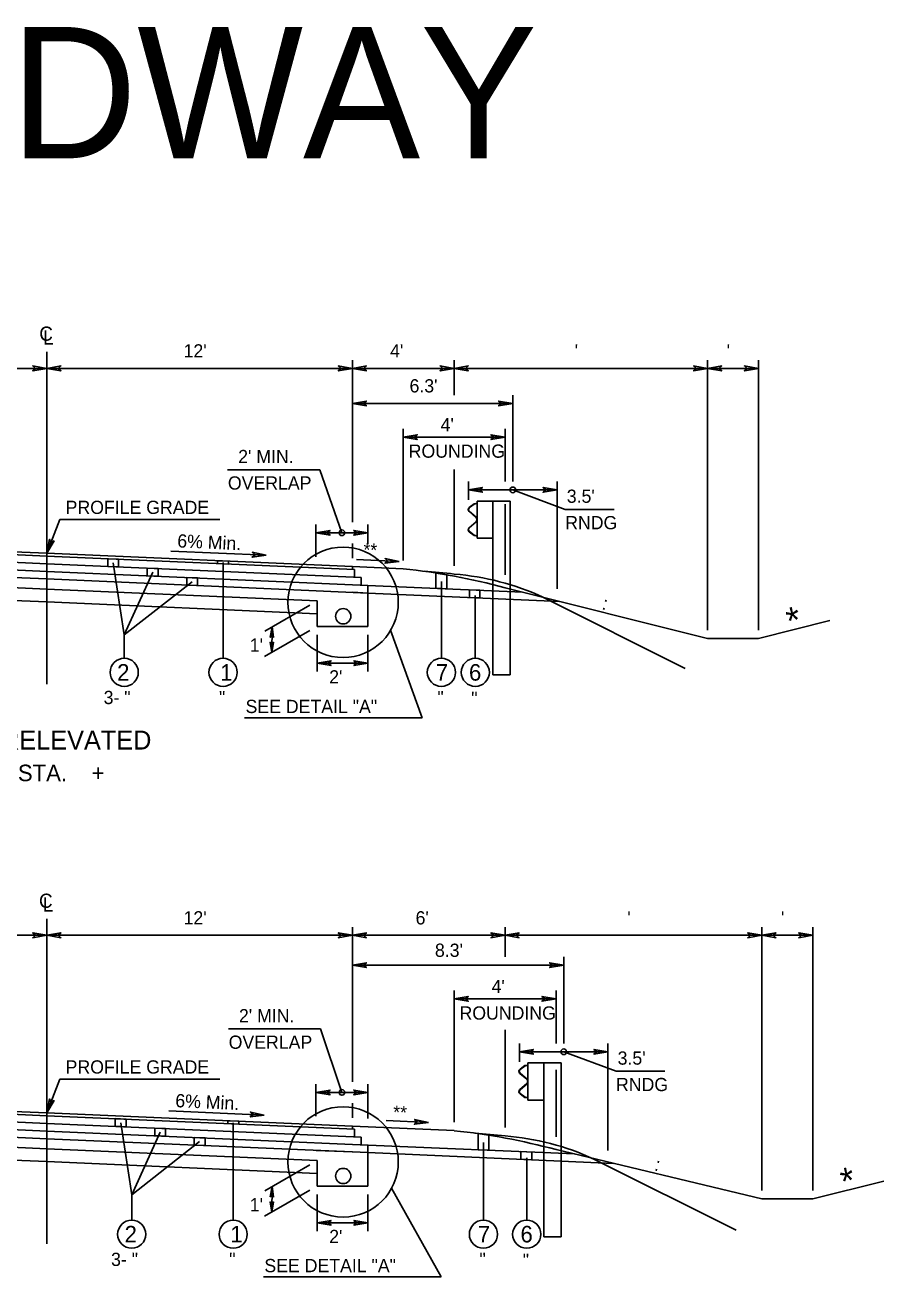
# Model space of a CAD drawing. Extents: x -540 to 1231, y -564 to 421.
# Drawn here: x 1120.2 to 1211.1, y 191.2 to 323.7 of the extents above; entities that cross this region are included whole.
import ezdxf

# ---------------------------------------------------------------- set-up
doc = ezdxf.new("R2010")
doc.units = 0
doc.layers.add('1', color=7, linetype='Continuous')
doc.layers.add('Des_ Drain_ Ftrs', color=7, linetype='Continuous')

msp = doc.modelspace()

# ---------------------------------------------------------------- linework, layer by layer
at = {"layer": '1'}
for p, q in [((1122.51, 253.91), (1122.51, 289.09)), ((1154.84, 271.06), (1154.84, 288.21)), ((1165.61, 284.5), (1165.61, 288.21)), ((1192.43, 259.63), (1192.43, 288.21)), ((1197.82, 259.63), (1197.82, 288.21)), ((1122.51, 287.33), (1090.18, 287.33)), ((1122.51, 287.33), (1154.84, 287.33)), ((1154.84, 287.33), (1165.61, 287.33)), ((1165.61, 287.33), (1192.43, 287.33)), ((1192.43, 287.33), (1197.82, 287.33)), ((1154.84, 283.62), (1171.81, 283.62)), ((1171.81, 275.35), (1171.81, 284.5)), ((1160.23, 267), (1160.23, 280.93)), ((1171, 275.35), (1171, 280.93)), ((1160.23, 280.05), (1171, 280.05)), ((1141.63, 276.6), (1151.4, 276.6)), ((1153.74, 269.93), (1151.4, 276.6)), ((1165.61, 266.44), (1165.61, 276.64)), ((1167.12, 273.4), (1167.12, 275.35)), ((1167.12, 274.47), (1176.51, 274.47)), ((1171.81, 274.47), (1177.37, 272.4)), ((1176.51, 263.99), (1176.51, 275.35)), ((1167.72, 273), (1167.2, 272.61)), ((1167.73, 272.97), (1167.22, 272.59)), ((1168.03, 273.06), (1167.72, 273)), ((1168.03, 273.03), (1167.73, 272.97)), ((1168.03, 273.28), (1168.03, 269.35)), ((1168.03, 273.28), (1169.72, 273.28)), ((1169.72, 273.28), (1169.72, 254.89)), ((1171.54, 273.28), (1169.72, 273.28)), ((1171, 265.47), (1171, 272.97)), ((1171.54, 273.28), (1171.54, 254.89)), ((1167.19, 272.18), (1167.92, 271.54)), ((1167.21, 272.2), (1167.94, 271.57)), ((1177.37, 272.4), (1182.53, 272.4)), ((1122.51, 267.76), (1123.88, 271.34)), ((1140.8, 271.34), (1123.88, 271.34)), ((1150.99, 267.4), (1150.99, 270.81)), ((1156.48, 268.73), (1156.48, 270.81)), ((1167.92, 271.09), (1167.19, 270.46)), ((1167.94, 271.07), (1167.21, 270.44)), ((1168, 271.36), (1168, 271.28)), ((1168.03, 271.36), (1168.03, 271.28)), ((1122.51, 267.76), (1090.17, 269.18)), ((1150.99, 269.93), (1156.48, 269.93)), ((1167.2, 270.03), (1167.72, 269.64)), ((1167.22, 270.05), (1167.73, 269.66)), ((1167.72, 269.64), (1168.03, 269.58)), ((1167.73, 269.66), (1168.03, 269.61)), ((1168.03, 269.35), (1169.72, 269.35)), ((1122.51, 266.65), (1088.91, 268.12)), ((1122.51, 267.46), (1089.83, 268.89)), ((1154.84, 266.35), (1122.51, 267.76)), ((1135.62, 267.99), (1145.73, 267.55)), ((1154.84, 267.23), (1154.84, 268.8)), ((1122.51, 265.84), (1087.99, 267.35)), ((1122.51, 265.04), (1088, 266.54)), ((1155.08, 266.04), (1122.51, 267.46)), ((1155.78, 265.2), (1122.51, 266.65)), ((1129.53, 266.75), (1130.7, 259.13)), ((1141.16, 266.79), (1141.16, 256.64)), ((1160.23, 266.12), (1154.84, 266.35)), ((1154.84, 266.35), (1154.84, 266.05)), ((1159.78, 266.89), (1155.29, 267.09)), ((1122.51, 263.96), (1093.38, 265.23)), ((1156.48, 264.36), (1122.51, 265.84)), ((1151, 263.79), (1122.51, 265.04)), ((1133.71, 265.77), (1130.7, 259.13)), ((1155.08, 266.04), (1155.08, 265.23)), ((1155.78, 265.2), (1155.78, 264.39)), ((1167.12, 265.34), (1167.12, 265.34)), ((1122.51, 262.61), (1093.38, 263.88)), ((1151.1, 262.71), (1122.51, 263.96)), ((1137.88, 264.75), (1130.7, 259.13)), ((1156.48, 263.55), (1151, 263.79)), ((1156.48, 264.36), (1156.48, 263.55)), ((1172.83, 263.65), (1156.48, 264.36)), ((1164.26, 264.76), (1164.26, 256.64)), ((1171, 264.11), (1192.43, 258.75)), ((1151.1, 261.36), (1122.51, 262.61)), ((1151.1, 260.01), (1151.1, 262.71)), ((1151.1, 262.71), (1151.1, 262.71)), ((1156.5, 263.55), (1154.84, 263.63)), ((1156.48, 260.01), (1156.48, 263.55)), ((1176.75, 262.67), (1156.48, 263.55)), ((1167.85, 263.28), (1167.85, 256.64)), ((1175.01, 263.11), (1190.06, 255.58)), ((1150.33, 262.27), (1145.58, 259.52)), ((1146.34, 259.96), (1146.32, 257.26)), ((1151.1, 260.01), (1156.48, 260.01)), ((1205.35, 260.63), (1197.82, 258.75)), ((1130.7, 259.13), (1130.7, 256.64)), ((1150.33, 259.57), (1145.56, 256.82)), ((1151.1, 259.13), (1151.1, 255.25)), ((1156.48, 259.13), (1156.48, 255.25)), ((1158.89, 259.62), (1162.22, 250.35)), ((1192.43, 258.75), (1197.82, 258.75)), ((1151.1, 256.13), (1156.48, 256.13)), ((1171.54, 254.89), (1169.72, 254.89)), ((1143.44, 250.35), (1162.22, 250.35)), ((1122.51, 194.69), (1122.51, 229.09)), ((1154.84, 211.83), (1154.84, 228.21)), ((1171, 225.05), (1171, 228.21)), ((1198.17, 200.31), (1198.17, 228.21)), ((1203.56, 200.31), (1203.56, 228.21)), ((1122.51, 227.33), (1090.18, 227.33)), ((1122.51, 227.33), (1154.84, 227.33)), ((1154.84, 227.33), (1171, 227.33)), ((1171, 227.33), (1198.17, 227.33)), ((1198.17, 227.33), (1203.56, 227.33)), ((1154.84, 224.17), (1177.2, 224.17)), ((1177.2, 215.89), (1177.2, 225.05)), ((1165.61, 207.54), (1165.61, 221.48)), ((1176.39, 215.89), (1176.39, 221.48)), ((1165.61, 220.6), (1176.39, 220.6)), ((1141.72, 217.42), (1151.48, 217.42)), ((1153.74, 210.71), (1151.48, 217.42)), ((1171, 206.98), (1171, 217.33)), ((1172.51, 213.94), (1172.51, 215.89)), ((1172.51, 215.01), (1181.89, 215.01)), ((1177.2, 215.01), (1182.75, 212.94)), ((1181.89, 204.55), (1181.89, 215.89)), ((1173.1, 213.55), (1172.59, 213.16)), ((1173.12, 213.52), (1172.6, 213.13)), ((1173.42, 213.6), (1173.1, 213.55)), ((1173.42, 213.57), (1173.12, 213.52)), ((1173.42, 213.83), (1173.42, 209.9)), ((1173.42, 213.83), (1175.1, 213.83)), ((1175.1, 213.83), (1175.1, 195.43)), ((1176.93, 213.83), (1175.1, 213.83)), ((1176.93, 213.83), (1176.93, 195.43)), ((1122.51, 208.54), (1123.88, 212.12)), ((1140.8, 212.12), (1123.88, 212.12)), ((1172.57, 212.72), (1173.3, 212.09)), ((1172.59, 212.75), (1173.32, 212.11)), ((1176.39, 206.02), (1176.39, 213.09)), ((1182.75, 212.94), (1187.91, 212.94)), ((1150.99, 208.18), (1150.99, 211.59)), ((1150.99, 210.71), (1156.48, 210.71)), ((1156.48, 207.94), (1156.48, 211.59)), ((1173.3, 211.64), (1172.57, 211)), ((1173.32, 211.62), (1172.59, 210.98)), ((1173.39, 211.9), (1173.39, 211.83)), ((1173.42, 211.9), (1173.42, 211.83)), ((1122.51, 208.24), (1089.83, 209.67)), ((1122.51, 208.54), (1090.17, 209.95)), ((1154.84, 208.01), (1154.84, 209.58)), ((1172.59, 210.57), (1173.1, 210.18)), ((1172.6, 210.59), (1173.12, 210.21)), ((1173.1, 210.18), (1173.42, 210.13)), ((1173.12, 210.21), (1173.42, 210.16)), ((1173.42, 209.9), (1175.1, 209.9)), ((1122.51, 206.62), (1087.99, 208.13)), ((1122.51, 207.43), (1088.91, 208.9)), ((1154.84, 207.13), (1122.51, 208.54)), ((1155.08, 206.82), (1122.51, 208.24)), ((1135.41, 208.75), (1145.52, 208.31)), ((1122.51, 205.81), (1087.99, 207.32)), ((1155.78, 205.98), (1122.51, 207.43)), ((1130.33, 207.49), (1131.49, 199.87)), ((1142.23, 207.5), (1142.23, 197.19)), ((1165.61, 206.66), (1154.84, 207.13)), ((1154.84, 207.13), (1154.84, 206.83)), ((1155.08, 206.82), (1155.08, 206.01)), ((1162.9, 207.52), (1158.41, 207.72)), ((1122.51, 204.74), (1093.38, 206.01)), ((1156.48, 205.14), (1122.51, 206.62)), ((1156.48, 204.33), (1122.51, 205.81)), ((1134.5, 206.51), (1131.49, 199.87)), ((1138.68, 205.5), (1131.49, 199.87)), ((1155.78, 205.98), (1155.78, 205.17)), ((1168.71, 205.39), (1168.71, 197.19)), ((1172.51, 205.88), (1172.51, 205.88)), ((1122.51, 203.39), (1093.38, 204.66)), ((1151.1, 203.49), (1122.51, 204.74)), ((1154.84, 204.4), (1151, 204.57)), ((1156.48, 204.33), (1154.83, 204.4)), ((1156.48, 205.14), (1156.48, 204.33)), ((1156.48, 200.79), (1156.48, 204.33)), ((1182.45, 203.2), (1156.48, 204.33)), ((1178.33, 204.19), (1156.5, 205.14)), ((1176.39, 204.65), (1198.17, 199.43)), ((1151.1, 202.14), (1122.51, 203.39)), ((1150.33, 203.05), (1145.58, 200.3)), ((1151.1, 200.79), (1151.1, 203.49)), ((1151.1, 203.49), (1151.1, 203.49)), ((1173.29, 203.78), (1173.29, 197.19)), ((1180.39, 203.65), (1195.44, 196.12)), ((1150.33, 200.35), (1145.56, 197.6)), ((1146.34, 200.74), (1146.32, 198.03)), ((1151.1, 200.79), (1156.48, 200.79)), ((1158.99, 200.57), (1164.22, 191.18)), ((1211.09, 201.31), (1203.56, 199.43)), ((1131.49, 199.87), (1131.49, 197.19)), ((1151.1, 199.91), (1151.1, 196.03)), ((1156.48, 199.91), (1156.48, 196.03)), ((1198.17, 199.43), (1203.56, 199.43)), ((1151.1, 196.91), (1156.48, 196.91)), ((1176.93, 195.43), (1175.1, 195.43)), ((1145.43, 191.18), (1164.22, 191.18))]:
    msp.add_line(p, q, dxfattribs=at)
for points in [[(1128.96, 267.18), (1130.1, 267.13), (1130.1, 266.32), (1128.96, 266.37)], [(1140.58, 266.97), (1141.73, 266.92), (1141.73, 266.62), (1140.58, 266.67)], [(1133.13, 266.19), (1134.28, 266.14), (1134.28, 265.33), (1133.13, 265.38)], [(1137.31, 265.2), (1138.46, 265.15), (1138.46, 264.34), (1137.31, 264.39)], [(1163.69, 265.67), (1164.84, 265.48), (1164.84, 264), (1163.69, 264.05)], [(1167.24, 263.89), (1168.34, 263.85), (1168.34, 263.04), (1167.24, 263.09)], [(1129.75, 207.93), (1130.9, 207.88), (1130.9, 207.07), (1129.75, 207.12)], [(1133.93, 206.93), (1135.08, 206.88), (1135.08, 206.08), (1133.93, 206.13)], [(1141.66, 207.71), (1142.81, 207.66), (1142.81, 207.36), (1141.66, 207.41)], [(1138.1, 205.94), (1139.25, 205.89), (1139.25, 205.08), (1138.1, 205.13)], [(1168.14, 206.35), (1169.28, 206.18), (1169.28, 204.58), (1168.14, 204.63)], [(1172.67, 204.44), (1173.82, 204.39), (1173.82, 203.58), (1172.67, 203.63)]]:
    msp.add_lwpolyline(points, close=True, dxfattribs=at)
for centre, radius in [((1171.81, 274.47), 0.3), ((1153.74, 269.93), 0.3), ((1153.86, 262.57), 5.84), ((1153.87, 261.09), 0.808), ((1130.7, 255.16), 1.49), ((1141.16, 255.16), 1.49), ((1164.26, 255.16), 1.49), ((1167.85, 255.16), 1.49), ((1177.2, 215.01), 0.3), ((1153.74, 210.71), 0.3), ((1153.86, 203.35), 5.84), ((1153.87, 201.86), 0.808), ((1131.49, 195.7), 1.49), ((1142.23, 195.7), 1.49), ((1168.71, 195.7), 1.49), ((1173.29, 195.7), 1.49)]:
    msp.add_circle(centre, radius, dxfattribs=at)
for centre, radius, start, end in [((1167.37, 272.39), 0.278, 126.9799, 229.021), ((1167.37, 272.39), 0.249, 126.9799, 229.021), ((1167.37, 270.25), 0.278, 130.979, 233.0201), ((1167.37, 270.25), 0.249, 130.979, 233.0201), ((1167.76, 271.36), 0.249, 0, 49.0365), ((1167.76, 271.28), 0.249, 310.9635, 0), ((1167.76, 271.36), 0.278, 0, 49.0365), ((1167.76, 271.28), 0.278, 310.9635, 0), ((1153.34, 199.28), 67.19, 74.7593, 84.1179), ((1154.8, 164.9), 101.24, 83.8633, 85.6775), ((1163.5, 238.27), 27.37, 65.1374, 85.5513), ((1172.75, 212.93), 0.278, 126.9799, 229.021), ((1172.75, 212.93), 0.249, 126.9799, 229.021), ((1173.14, 211.9), 0.249, 0, 49.0365), ((1173.14, 211.9), 0.278, 0, 49.0365), ((1172.75, 210.79), 0.278, 130.979, 233.0201), ((1172.75, 210.79), 0.249, 130.979, 233.0201), ((1173.14, 211.83), 0.249, 310.9635, 0), ((1173.14, 211.83), 0.278, 310.9635, 0), ((1158.73, 139.82), 67.19, 74.7602, 84.1188), ((1160.18, 105.44), 101.24, 83.8633, 85.6775), ((1168.88, 178.82), 27.37, 65.1374, 85.5513)]:
    msp.add_arc(centre, radius, start, end, dxfattribs=at)
at = {"layer": 'Des_ Drain_ Ftrs'}
for points in [[(1122.51, 287.33), (1121.02, 287.08), (1121.31, 287.33), (1121.02, 287.58)], [(1122.51, 287.33), (1124, 287.08), (1123.7, 287.33), (1124, 287.58)], [(1154.84, 287.33), (1153.35, 287.08), (1153.64, 287.33), (1153.35, 287.58)], [(1154.84, 287.33), (1156.33, 287.08), (1156.03, 287.33), (1156.33, 287.58)], [(1165.61, 287.33), (1164.13, 287.08), (1164.42, 287.33), (1164.13, 287.58)], [(1165.61, 287.33), (1167.1, 287.08), (1166.81, 287.33), (1167.1, 287.58)], [(1192.43, 287.33), (1190.94, 287.08), (1191.24, 287.33), (1190.94, 287.58)], [(1192.43, 287.33), (1193.92, 287.08), (1193.62, 287.33), (1193.92, 287.58)], [(1197.82, 287.33), (1196.33, 287.08), (1196.63, 287.33), (1196.33, 287.58)], [(1154.84, 283.62), (1156.33, 283.38), (1156.03, 283.62), (1156.33, 283.87)], [(1171.81, 283.62), (1170.32, 283.38), (1170.62, 283.62), (1170.32, 283.87)], [(1160.23, 280.05), (1161.71, 279.8), (1161.42, 280.05), (1161.71, 280.3)], [(1171, 280.05), (1169.51, 279.8), (1169.81, 280.05), (1169.51, 280.3)], [(1167.12, 274.47), (1168.61, 274.22), (1168.31, 274.47), (1168.61, 274.72)], [(1176.51, 274.47), (1175.02, 274.22), (1175.31, 274.47), (1175.02, 274.72)], [(1122.51, 267.76), (1123.27, 269.06), (1122.93, 268.88), (1122.81, 269.24)], [(1150.99, 269.93), (1152.48, 269.68), (1152.19, 269.93), (1152.48, 270.18)], [(1156.48, 269.93), (1154.99, 269.68), (1155.29, 269.93), (1154.99, 270.18)], [(1145.73, 267.55), (1144.23, 267.36), (1144.54, 267.6), (1144.25, 267.86)], [(1159.78, 266.89), (1158.28, 266.7), (1158.59, 266.94), (1158.31, 267.2)], [(1146.34, 259.96), (1146.15, 258.88), (1146.33, 259.09), (1146.51, 258.88)], [(1146.32, 257.26), (1146.14, 258.34), (1146.32, 258.13), (1146.51, 258.34)], [(1151.1, 256.13), (1152.58, 255.88), (1152.29, 256.13), (1152.58, 256.38)], [(1156.48, 256.13), (1155, 255.88), (1155.29, 256.13), (1155, 256.38)], [(1122.51, 227.33), (1121.02, 227.08), (1121.31, 227.33), (1121.02, 227.58)], [(1122.51, 227.33), (1124, 227.08), (1123.7, 227.33), (1124, 227.58)], [(1154.84, 227.33), (1153.35, 227.08), (1153.64, 227.33), (1153.35, 227.58)], [(1154.84, 227.33), (1156.33, 227.08), (1156.03, 227.33), (1156.33, 227.58)], [(1171, 227.33), (1169.51, 227.08), (1169.81, 227.33), (1169.51, 227.58)], [(1171, 227.33), (1172.49, 227.08), (1172.19, 227.33), (1172.49, 227.58)], [(1198.17, 227.33), (1196.68, 227.08), (1196.97, 227.33), (1196.68, 227.58)], [(1198.17, 227.33), (1199.66, 227.08), (1199.36, 227.33), (1199.66, 227.58)], [(1203.56, 227.33), (1202.07, 227.08), (1202.36, 227.33), (1202.07, 227.58)], [(1154.84, 224.17), (1156.32, 223.92), (1156.03, 224.17), (1156.32, 224.42)], [(1177.2, 224.17), (1175.71, 223.92), (1176, 224.17), (1175.71, 224.42)], [(1165.61, 220.6), (1167.1, 220.35), (1166.81, 220.6), (1167.1, 220.84)], [(1176.39, 220.6), (1174.9, 220.35), (1175.2, 220.6), (1174.9, 220.84)], [(1172.51, 215.01), (1173.99, 214.76), (1173.7, 215.01), (1173.99, 215.26)], [(1181.89, 215.01), (1180.4, 214.76), (1180.7, 215.01), (1180.4, 215.26)], [(1150.99, 210.71), (1152.48, 210.46), (1152.19, 210.71), (1152.48, 210.95)], [(1156.48, 210.71), (1154.99, 210.46), (1155.29, 210.71), (1154.99, 210.95)], [(1122.51, 208.54), (1123.27, 209.84), (1122.93, 209.66), (1122.81, 210.02)], [(1145.52, 208.31), (1144.03, 208.13), (1144.33, 208.36), (1144.05, 208.62)], [(1162.9, 207.52), (1161.41, 207.34), (1161.71, 207.58), (1161.43, 207.84)], [(1146.34, 200.74), (1146.15, 199.66), (1146.33, 199.87), (1146.51, 199.65)], [(1146.32, 198.03), (1146.14, 199.12), (1146.32, 198.9), (1146.51, 199.12)], [(1151.1, 196.91), (1152.58, 196.66), (1152.29, 196.91), (1152.58, 197.16)], [(1156.48, 196.91), (1155, 196.66), (1155.29, 196.91), (1155, 197.16)]]:
    msp.add_lwpolyline(points, close=True, dxfattribs=at)

# ---------------------------------------------------------------- texts
at = {"layer": '1'}
for s, height, p in [("24' ROADWAY", 13.8979, (1049, 309.56)), ("12'", 1.4, (1136.98, 288.48)), ("4'", 1.4, (1158.83, 288.48)), ("  '", 1.4, (1177.33, 288.48)), (" '", 1.4, (1193.93, 288.48)), ("6.3'", 1.4, (1160.89, 284.78)), ("4'", 1.4, (1164.18, 280.67)), ("2' MIN.", 1.4, (1142.76, 277.3)), ('ROUNDING', 1.4, (1160.8, 277.87)), ('OVERLAP', 1.4, (1141.67, 274.5)), ("3.5'", 1.4, (1177.53, 273.1)), ('PROFILE GRADE', 1.4, (1124.5, 271.92)), ('RNDG', 1.4, (1177.36, 270.3)), ('2', 1.75, (1129.95, 254.28)), ('1', 1.75, (1140.86, 254.28)), ('7', 1.75, (1163.67, 254.28)), ('6', 1.75, (1167.18, 254.28)), ("2'", 1.4, (1152.39, 253.98)), ('3- "', 1.4, (1128.52, 251.8)), (' "', 1.4, (1140.21, 251.8)), (' "', 1.4, (1163.32, 251.8)), (' "', 1.4, (1166.9, 251.7)), ('SEE DETAIL "A"', 1.4, (1143.54, 250.85)), ('SUPERELEVATED', 2, (1110.39, 246.99)), ('STA.    +      TO STA.    +     ', 1.75, (1102.48, 243.64)), ("12'", 1.4, (1136.98, 228.48)), ("6'", 1.4, (1161.53, 228.48)), ("  '", 1.4, (1182.89, 228.48)), (" '", 1.4, (1199.67, 228.48)), ("8.3'", 1.4, (1163.58, 225.05)), ("4'", 1.4, (1169.57, 221.21)), ("2' MIN.", 1.4, (1142.84, 218.12)), ('ROUNDING', 1.4, (1166.18, 218.41)), ('OVERLAP', 1.4, (1141.75, 215.32)), ("3.5'", 1.4, (1182.91, 213.64)), ('PROFILE GRADE', 1.4, (1124.5, 212.7)), ('RNDG', 1.4, (1182.74, 210.84)), ('2', 1.75, (1130.74, 194.83)), ('1', 1.75, (1141.93, 194.83)), ("2'", 1.4, (1152.39, 194.76)), ('7', 1.75, (1168.12, 194.83)), ('6', 1.75, (1172.63, 194.83)), ('3- "', 1.4, (1129.31, 192.34)), (' "', 1.4, (1141.29, 192.34)), (' "', 1.4, (1167.77, 192.34)), (' "', 1.4, (1172.35, 192.24)), ('SEE DETAIL "A"', 1.4, (1145.53, 191.68))]:
    msp.add_text(s, height=height, dxfattribs=at).set_placement(p)
for s, height, rotation, p in [('6% Min.', 1.4, 357.373, (1136.29, 268.39)), ('**', 1.4, 357.2164, (1155.97, 267.45)), (' : ', 1.4, 345.7718, (1180.67, 261.98)), ('*', 2.8, 12.8479, (1201.13, 259.15)), ("1'", 1.4, 0.1438, (1143.99, 257.35)), ('6% Min.', 1.4, 357.3727, (1136.08, 209.15)), ('**', 1.4, 357.2166, (1159.12, 207.93)), (' : ', 1.4, 345.7718, (1186.22, 202.6)), ('*', 2.8, 12.8479, (1206.87, 199.84)), ("1'", 1.4, 0.1438, (1143.99, 198.12))]:
    msp.add_text(s, height=height, rotation=rotation, dxfattribs=at).set_placement(p)
at = {"layer": 'Des_ Drain_ Ftrs'}
for s, p in [('C', (1121.71, 290.25)), ('L', (1122.11, 289.85)), ('C', (1121.68, 230.24)), ('L', (1122.08, 229.85))]:
    msp.add_text(s, height=1.5, dxfattribs=at).set_placement(p)

doc.saveas('drawing.dxf')
